(* Logix 5000 project; controller ZaxisVmpEdsSample 1769-L16ER-BB1B rev 30.11; software revision 30.00 *)

TASK MainTask (continuous, watchdog 500 ms) : MainProgram

MODULES
   Local : 1769-L16ER-BB1B (PointIO 0, rev 30.11)
      VMP_01 : vendor 1449 type 43 code 17 (Ethernet 192.168.168.135, rev 1.1, StandardDataDriven RPI 20 ms)
      Discrete_IO : Embedded (PointIO 1, rev 30.11, Output RPI 20 ms)
           Local:1:I.Data.0   // Green Push Btn
           Local:1:I.Data.1   // Red Push Btn
           Local:1:O   // Green Run Light
END_MODULES

TYPE VMP_Prg :
STRUCT
   CalDispenseTime : BOOL;   // CalDispenseTime
   Direction : BOOL;   // Direction CCW
   SetShotSize : BOOL;   // Set Volume
   ContinuousRun : BOOL;   // Run Continuously
   Spare1_4 : BOOL;   // Spare Bit
   Spare1_5 : BOOL;   // Spare Bit
   Spare1_6 : BOOL;   // Spare Bit
   Spare1_7 : BOOL;   // Spare Bit
   Spare1_8 : BOOL;   // Spare Bit
   Spare1_9 : BOOL;   // Spare Bit
   Spare1_10 : BOOL;   // Spare Bit
   Spare1_11 : BOOL;   // Spare Bit
   Spare1_12 : BOOL;   // Spare Bit
   Spare1_13 : BOOL;   // Spare Bit
   Spare1_14 : BOOL;   // Spare Bit
   Spare1_15 : BOOL;   // Spare Bit
   Spare1_16 : BOOL;   // Spare Bit
   Spare1_17 : BOOL;   // Spare Bit
   Spare1_18 : BOOL;   // Spare Bit
   Spare1_19 : BOOL;   // Spare Bit
   Spare1_20 : BOOL;   // Spare Bit
   Spare1_21 : BOOL;   // Spare Bit
   Spare1_22 : BOOL;   // Spare Bit
   Spare1_23 : BOOL;   // Spare Bit
   Spare1_24 : BOOL;   // Spare Bit
   Spare1_25 : BOOL;   // Spare Bit
   Spare1_26 : BOOL;   // Spare Bit
   Spare1_27 : BOOL;   // Spare Bit
   Spare1_28 : BOOL;   // Spare Bit
   Spare1_29 : BOOL;   // Spare Bit
   Spare1_30 : BOOL;   // Spare Bit
   Spare1_31 : BOOL;   // Spare Bit
   Program : DINT;   // Program
   PullBack : DINT;   // PullBack
   InitialRPM : DINT;   // InitialRPM
   RPM : DINT;   // RPM
   FinalRPM : DINT;   // FinalRPM
   FineAdjust : DINT;   // FineAdjust
   Acceleration : DINT;   // Acceleration
   Deceleration : DINT;   // Deceleration
   LoopCycles : DINT;   // LoopCycles
   LinkedProgram : DINT;   // LinkedProgram
   LinkedTimeDelay : DINT;   // LinkedTimeDelay
   MotorCurrent : DINT;   // MotorCurrent
   Revolutions : DINT;   // Revolutions
   AprxDispenseTime : DINT;   // DispenseTime
   Volume : REAL;   // Volume
   ProgramName : STRING;   // ProgramName
END_STRUCT
END_TYPE

TYPE VMP_Setup :
STRUCT
   ReadyInterlock : BOOL;   // RdyInputEnabled
   EthernetRunReady : BOOL;   // EthSendBusy
   HoldOnFault : BOOL;   // HoldOnFault
   Spare1_3 : BOOL;   // Spare Bit
   Spare1_4 : BOOL;   // Spare Bit
   Spare1_5 : BOOL;   // Spare Bit
   Spare1_6 : BOOL;   // Spare Bit
   Spare1_7 : BOOL;   // Spare Bit
   Spare1_8 : BOOL;   // Spare Bit
   Spare1_9 : BOOL;   // Spare Bit
   Spare1_10 : BOOL;   // Spare Bit
   Spare1_11 : BOOL;   // Spare Bit
   Spare1_12 : BOOL;   // Spare Bit
   Spare1_13 : BOOL;   // Spare Bit
   Spare1_14 : BOOL;   // Spare Bit
   Spare1_15 : BOOL;   // Spare Bit
   Spare1_16 : BOOL;   // Spare Bit
   Spare1_17 : BOOL;   // Spare Bit
   Spare1_18 : BOOL;   // Spare Bit
   Spare1_19 : BOOL;   // Spare Bit
   Spare1_20 : BOOL;   // Spare Bit
   Spare1_21 : BOOL;   // Spare Bit
   Spare1_22 : BOOL;   // Spare Bit
   Spare1_23 : BOOL;   // Spare Bit
   Spare1_24 : BOOL;   // Spare Bit
   Spare1_25 : BOOL;   // Spare Bit
   Spare1_26 : BOOL;   // Spare Bit
   Spare1_27 : BOOL;   // Spare Bit
   Spare1_28 : BOOL;   // Spare Bit
   Spare1_29 : BOOL;   // Spare Bit
   Spare1_30 : BOOL;   // Spare Bit
   Spare1_31 : BOOL;   // Spare Bit
   Baud : DINT;   // Baud
   PumpNumber : DINT;   // PumpNumber
   SpareDInt0 : DINT;   // SpareDInt0
   SpareDInt1 : DINT;   // SpareDInt1
   FirmwareRev : REAL;   // FirmRev
   Bore : REAL;   // Bore
   SpareReal0 : REAL;   // SpareReal0
   SpareReal1 : REAL;   // SpareReal1
   SerialNumber : STRING;   // SerialNumber
END_STRUCT
END_TYPE

TYPE VMP_TcpIP_Cfg :
STRUCT
   Status : DINT;   // Status
   Config_Capability : DINT;   // Capability
   Config_Control : DINT;   // IfCtrl
   Path_Size : INT;   // Epath
   Path : SINT[4];   // Padd
   IP_Address : DINT;   // IPAddr
   Network_Address : DINT;   // NetAddr
   Gateway_Address : DINT;   // GateWay
   Name_Server : DINT;   // DNS1
   Name_Server_2 : DINT;   // DNS2
   Domain_Name : STRING;   // Domain
   Host_Name : STRING;   // Host
   Safety_Network_Number : SINT[6];   // Ignore
   TTL : SINT;   // TTL
   Alloc_Control : SINT;   // MultCast
   Reserved : SINT;   // Reserved
   Num_Mcast : INT;   // MultCastAlloc
   Mcast_Start_Addr : DINT;   // MultCastStart
   Selected_Acd : BOOL;   // ACD
   Acd_Activity : SINT;   // ACDState
   Remote_MAC : SINT[6];   // MACRmt
   Arp_Pdu : SINT[28];   // ARP_PDU
   EthernetIP_Quick_Connect : BOOL;   // QuickCon
   Encp_Inactivity_Timeout : INT;   // InactTimeout
END_STRUCT
END_TYPE

VAR_GLOBAL   (* controller tags *)
   Dec_FineAdj : BOOL;
   ReadPrg : MESSAGE;
        MessageParameters(ServiceCode := 16#0001, DestinationTag := VMP_Program, ...)
   ReadSetup : MESSAGE;
        MessageParameters(ServiceCode := 16#0001, DestinationTag := VMP_Setup, ...)
   ReadTcpIp : MESSAGE;
        MessageParameters(ServiceCode := 16#0001, DestinationTag := VMP_TcpIp_Cfg, ...)
   VMP_Config : VMP_Setup;
   VMP_Program : VMP_Prg := (InitialRPM := 130, RPM := 200, FinalRPM := 130, Acceleration := 90, Deceleration := 200, LoopCycles := 1, LinkedProgram := -1, MotorCurrent := 80, AprxDispenseTime := 310, Volume := 0.1036815, ProgramName := 'Program 00');
   VMP_Setup : VMP_Setup := (Baud := 1152, PumpNumber := 1, FirmwareRev := 1.3, Bore := 0.25, SerialNumber := '123-17V3');
   VMP_TcpIp_Cfg : VMP_TcpIP_Cfg := (Status := 16#0000_0001, Config_Capability := 16#0000_0034, Path_Size := 3, Path[0] := 16#f6, Path[2] := 16#24, Path[3] := 16#01, IP_Address := 16#c0a8_a866, Network_Address := 16#ffff_ff00, Gateway_Address := 16#c0a8_0101);
   VMP_TcpIp_Read : BOOL;
   VMP_TcpIp_Write : BOOL;
   WritePrg : MESSAGE;
        MessageParameters(ServiceCode := 16#0002, LocalElement := VMP_Program, ...)
   WriteSetup : MESSAGE;
        MessageParameters(ServiceCode := 16#0002, LocalElement := VMP_Setup, ...)
   WriteTcpIp : MESSAGE;
        MessageParameters(ServiceCode := 16#0002, LocalElement := VMP_TcpIp_Cfg, ...)
END_VAR

PROGRAM MainProgram   (* main routine MainRoutine *)
VAR
   Fault : ALIAS FOR VMP_01:I.Adj_Sensor_Fault;
   Pmp_ReadyToRun : ALIAS FOR VMP_01:I.Ready_to_Run;   // VMP is read to run
   VMP_Prg_Read : BOOL;
   VMP_Prg_Write : BOOL;
   VMP_Setup_Read : BOOL;
   VMP_Setup_Write : BOOL;
END_VAR

ROUTINE MainRoutine   (* ladder *)
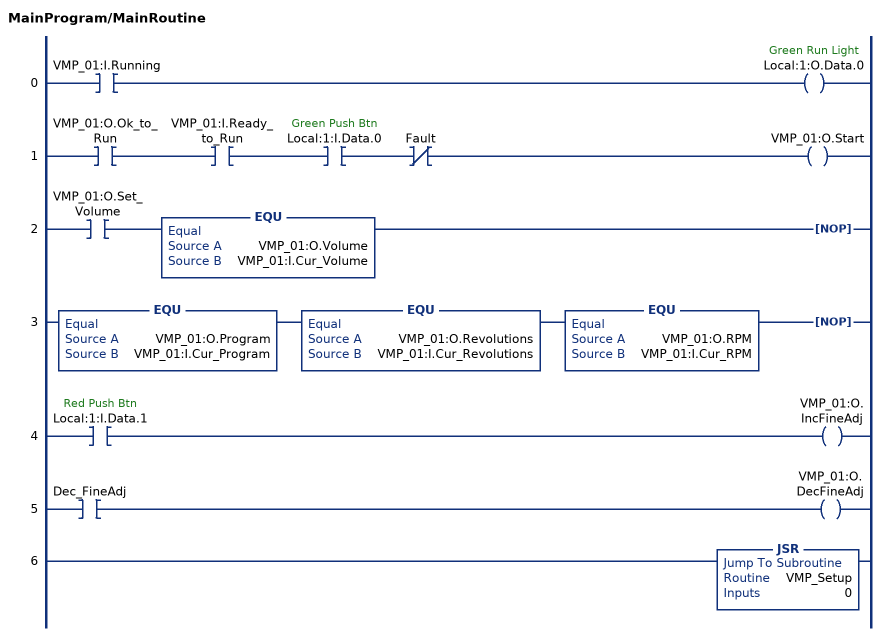
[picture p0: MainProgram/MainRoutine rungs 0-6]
   0: XIC(VMP_01:I.Running)OTE(Local:1:O.Data.0);
   1: XIC(VMP_01:O.Ok_to_Run)XIC(VMP_01:I.Ready_to_Run)XIC(Local:1:I.Data.0)XIO(Fault)OTE(VMP_01:O.Start);
   2: XIC(VMP_01:O.Set_Volume)EQU(VMP_01:O.Volume,VMP_01:I.Cur_Volume)NOP();
   3: EQU(VMP_01:O.Program,VMP_01:I.Cur_Program)EQU(VMP_01:O.Revolutions,VMP_01:I.Cur_Revolutions)EQU(VMP_01:O.RPM,VMP_01:I.Cur_RPM)NOP();
   4: XIC(Local:1:I.Data.1)OTE(VMP_01:O.IncFineAdj);
   5: XIC(Dec_FineAdj)OTE(VMP_01:O.DecFineAdj);
   6: JSR(VMP_Setup,0);
END_ROUTINE

ROUTINE VMP_Setup   (* ladder *)
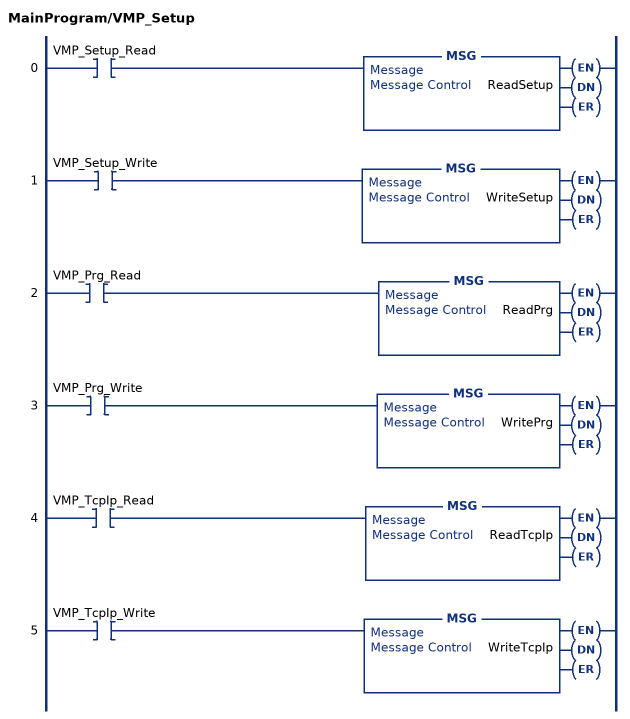
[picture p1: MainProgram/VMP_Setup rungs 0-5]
   0: XIC(VMP_Setup_Read)MSG(ReadSetup);
   1: XIC(VMP_Setup_Write)MSG(WriteSetup);
   2: XIC(VMP_Prg_Read)MSG(ReadPrg);
   3: XIC(VMP_Prg_Write)MSG(WritePrg);
   4: XIC(VMP_TcpIp_Read)MSG(ReadTcpIp);
   5: XIC(VMP_TcpIp_Write)MSG(WriteTcpIp);
END_ROUTINE
END_PROGRAM
